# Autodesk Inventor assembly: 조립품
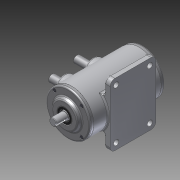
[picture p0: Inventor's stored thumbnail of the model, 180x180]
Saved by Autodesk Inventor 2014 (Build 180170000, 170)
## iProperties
Created: 2014-12
Part Number: 조립품
Document SubType Name: Assembly
Designer: Owner
Author: Owner
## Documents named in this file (10)
- C:\Users\Owner\Desktop\441223V1015\조립품.iam
- C:\Users\Owner\Desktop\441223V1015\M4-소켓머리.ipt
- C:\Users\Owner\Desktop\441223V1015\뒷커버.ipt
- C:\Users\Owner\Desktop\441223V1015\베어링 6203.ipt
- C:\Users\Owner\Desktop\441223V1015\본체.ipt
- C:\Users\Owner\Desktop\441223V1015\부시.ipt
- C:\Users\Owner\Desktop\441223V1015\슬라이더.ipt
- C:\Users\Owner\Desktop\441223V1015\앞커버.ipt
- C:\Users\Owner\Desktop\441223V1015\오일실.ipt
- C:\Users\Owner\Desktop\441223V1015\축.ipt
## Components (11 placed, 3 different names)
1. 7-베어링 6203:1
2. 8-오일실:1
3. 7-베어링 6203:2
4. 9-M4-소켓머리:1
5. 9-M4-소켓머리:3
6. 9-M4-소켓머리:4
7. 9-M4-소켓머리:5
8. 9-M4-소켓머리:2
9. 9-M4-소켓머리:6
10. 9-M4-소켓머리:7
11. 9-M4-소켓머리:8
